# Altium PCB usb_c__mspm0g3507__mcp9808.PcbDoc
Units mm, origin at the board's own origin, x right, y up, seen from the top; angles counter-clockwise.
Board outline 68 x 40 mm, 2 copper layers (Top, Bottom), stack 0 mm thick; 37 components, 30 nets, 190 pads, 69 vias.
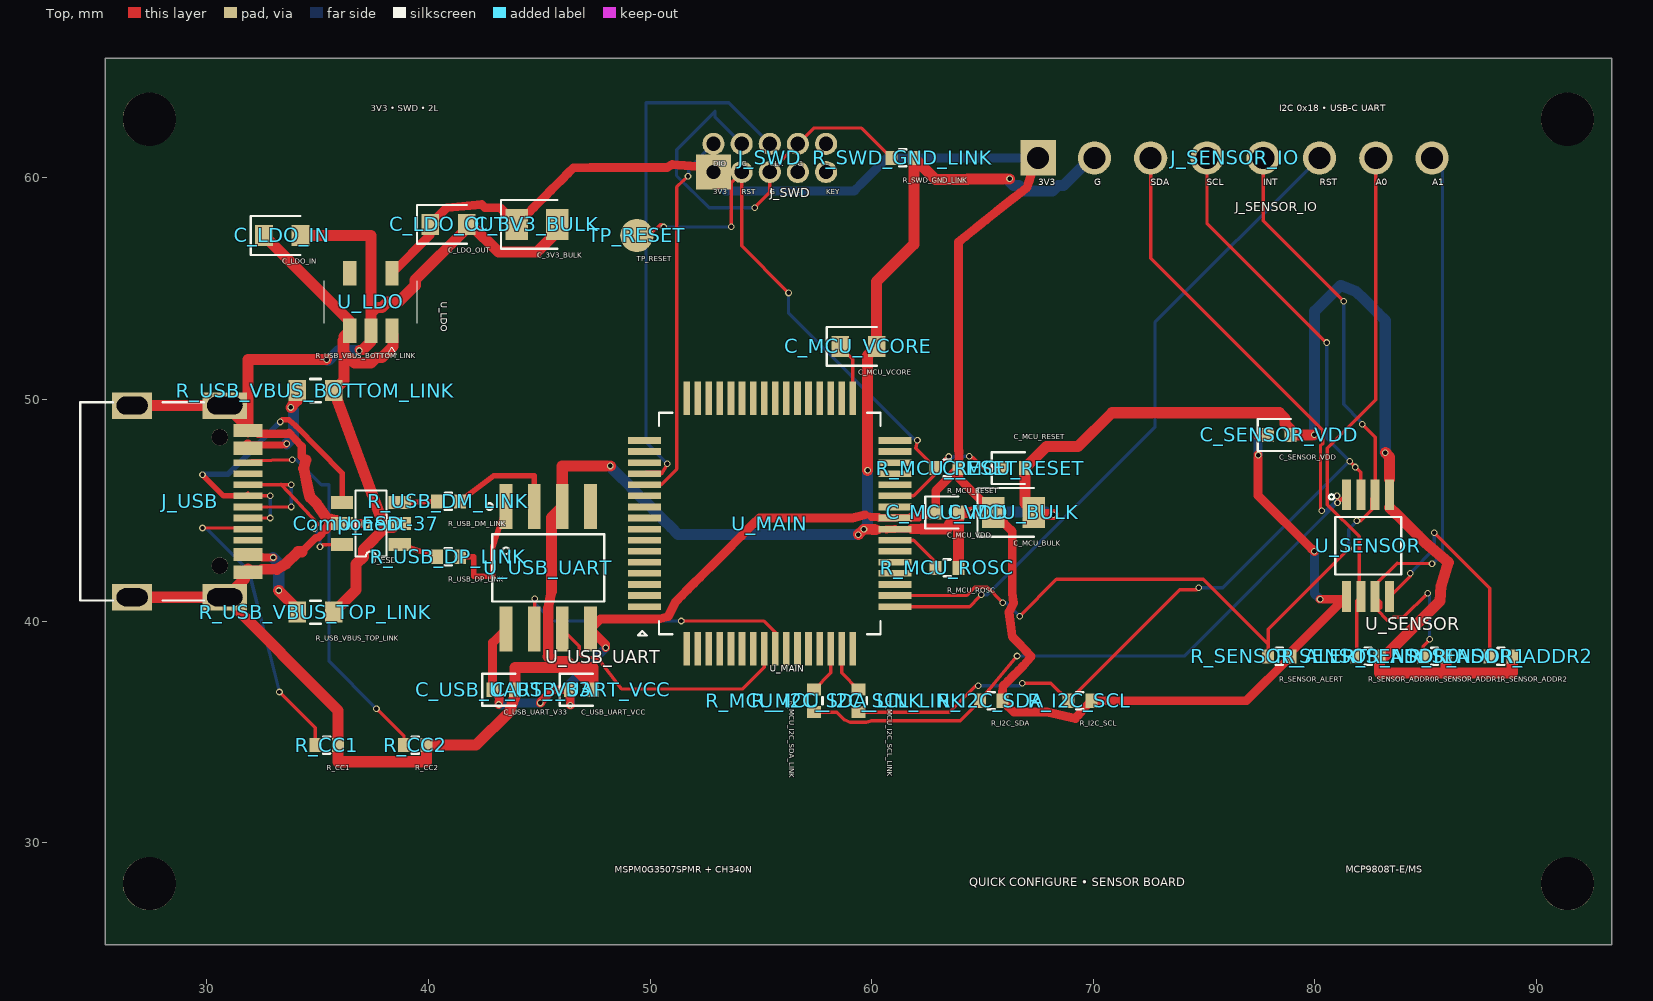
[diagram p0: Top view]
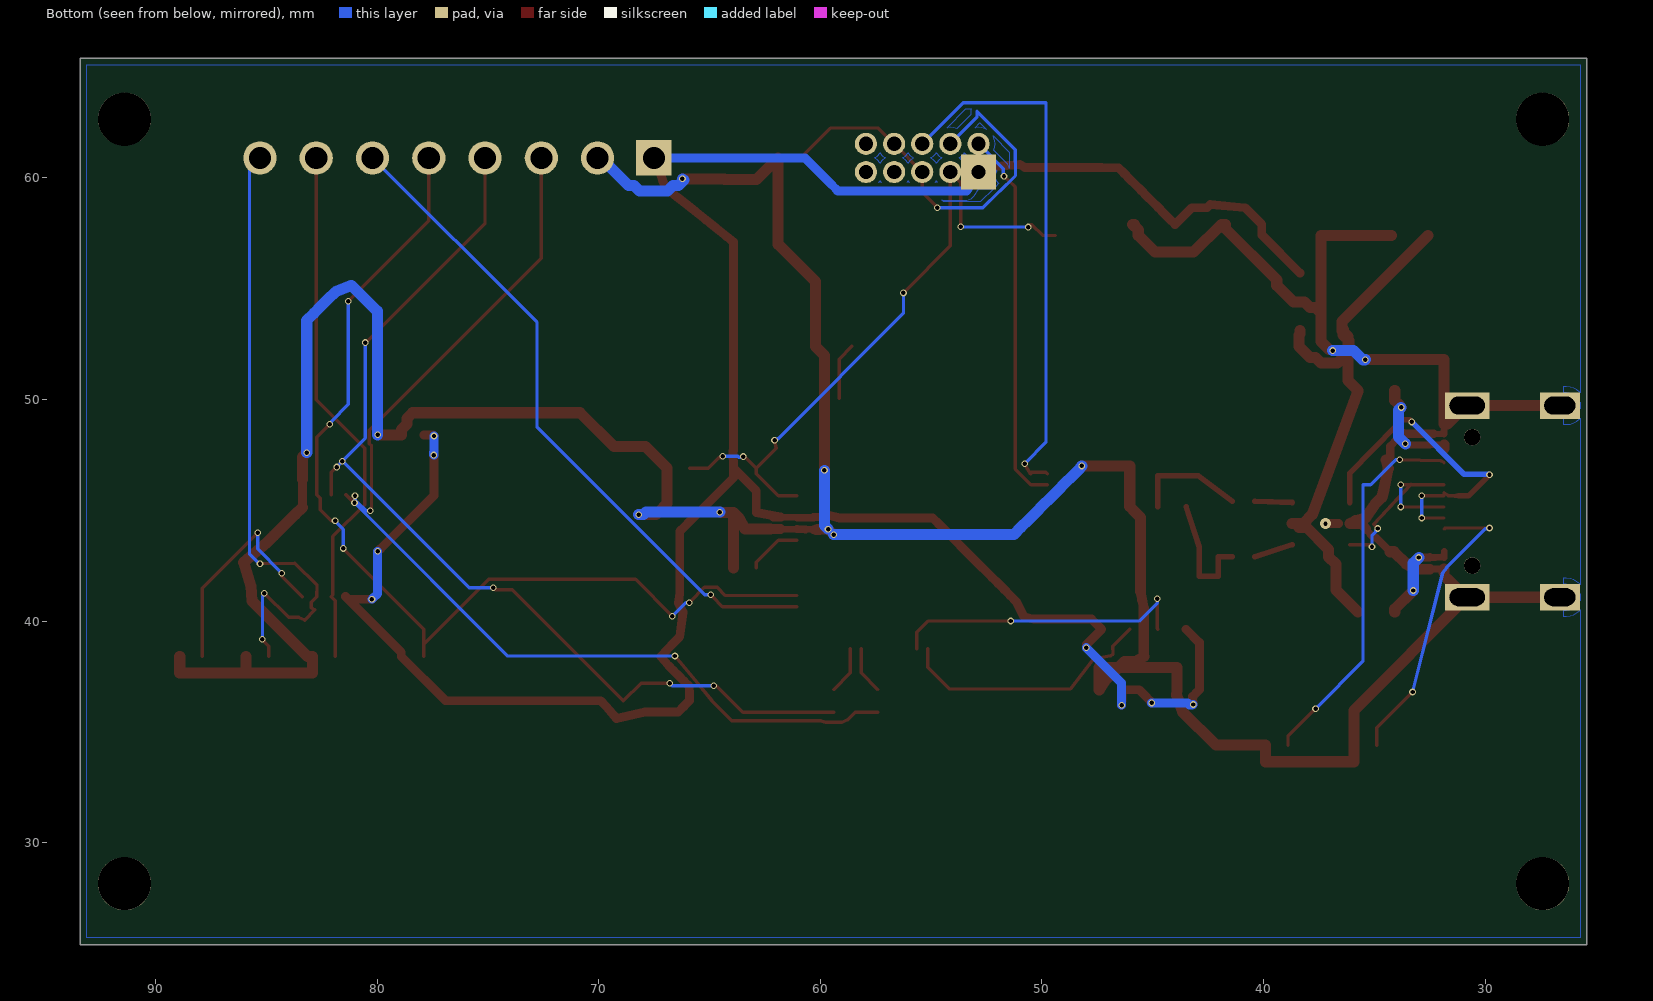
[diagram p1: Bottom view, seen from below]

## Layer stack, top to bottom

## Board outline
25.4,65.4 93.4,65.4 93.4,25.4 25.4,25.4

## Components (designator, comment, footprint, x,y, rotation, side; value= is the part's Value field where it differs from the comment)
C_3V3_BULK "" TSCIRCUIT-2.8500x1.4000mm 44.9,57.9 r0 top
C_LDO_IN "" TSCIRCUIT-2.4500x0.9500mm 33.4,57.4 r0 top
C_LDO_OUT "" TSCIRCUIT-2.4500x0.9500mm 40.9,57.9 r0 top
C_MCU_BULK "" TSCIRCUIT-2.8500x1.4000mm 66.4,44.9 r0 top
C_MCU_RESET "" TSCIRCUIT-1.5600x0.6400mm 66.4,46.9 r0 top
C_MCU_VCORE "" TSCIRCUIT-2.4500x0.9500mm 59.4,52.4 r0 top
C_MCU_VDD "" TSCIRCUIT-1.5600x0.6400mm 63.4,44.9 r0 top
C_SENSOR_VDD "" TSCIRCUIT-1.5600x0.6400mm 78.4,48.4 r0 top
C_USB_UART_V33 "" TSCIRCUIT-1.5600x0.6400mm 43.4,36.9 r0 top
C_USB_UART_VCC "" TSCIRCUIT-1.5600x0.6400mm 46.9,36.9 r0 top
Component-37 "" TSCIRCUIT-0.5000x0.5000mm 37.2,44.4 r0 top
J_SENSOR_IO "" TSCIRCUIT-19.2800x1.5000mm 76.4,60.9 r0 top
J_SWD "" TSCIRCUIT-6.0800x2.2700mm 55.4,60.9 r0 top
J_USB "" TSCIRCUIT-6.7732x9.8502mm 29.112,45.4 r90 top
R_CC1 "" TSCIRCUIT-1.5600x0.6400mm 35.4,34.4 r0 top
R_CC2 "" TSCIRCUIT-1.5600x0.6400mm 39.4,34.4 r0 top
R_I2C_SCL "" TSCIRCUIT-1.5600x0.6400mm 69.4,36.4 r0 top
R_I2C_SDA "" TSCIRCUIT-1.5600x0.6400mm 65.4,36.4 r0 top
R_MCU_I2C_SCL_LINK "" TSCIRCUIT-0.6400x1.5600mm 59.4,36.4 r270 top
R_MCU_I2C_SDA_LINK "" TSCIRCUIT-0.6400x1.5600mm 57.4,36.4 r270 top
R_MCU_RESET "" TSCIRCUIT-1.5600x0.6400mm 63.4,46.9 r0 top
R_MCU_ROSC "" TSCIRCUIT-1.5600x0.6400mm 63.4,42.4 r0 top
R_SENSOR_ADDR0 "" TSCIRCUIT-1.5600x0.6400mm 82.4,38.4 r0 top
R_SENSOR_ADDR1 "" TSCIRCUIT-1.5600x0.6400mm 85.4,38.4 r0 top
R_SENSOR_ADDR2 "" TSCIRCUIT-1.5600x0.6400mm 88.4,38.4 r0 top
R_SENSOR_ALERT "" TSCIRCUIT-1.5600x0.6400mm 78.4,38.4 r0 top
R_SWD_GND_LINK "" TSCIRCUIT-1.5600x0.6400mm 61.4,60.9 r0 top
R_USB_DM_LINK "" TSCIRCUIT-1.5600x0.6400mm 40.9,45.4 r0 top
R_USB_DP_LINK "" TSCIRCUIT-1.5600x0.6400mm 40.9,42.9 r0 top
R_USB_VBUS_BOTTOM_LINK "" TSCIRCUIT-2.4500x0.9500mm 34.9,50.4 r0 top
R_USB_VBUS_TOP_LINK "" TSCIRCUIT-2.4500x0.9500mm 34.9,40.4 r0 top
TP_RESET "" TSCIRCUIT-1.5000x1.5000mm 49.4,57.4 r0 top
U_ESD "" TSCIRCUIT-3.6000x2.5000mm 37.4,44.4 r0 top
U_LDO "" TSCIRCUIT-2.5000x3.7000mm 37.4,54.4 r270 top
U_MAIN "" TSCIRCUIT-12.8000x12.8000mm 55.4,44.4 r0 top
U_SENSOR "" TSCIRCUIT-2.3562x5.9969mm 82.4,43.4 r0 top
U_USB_UART "" TSCIRCUIT-4.3840x7.5712mm 45.4,42.4 r0 top

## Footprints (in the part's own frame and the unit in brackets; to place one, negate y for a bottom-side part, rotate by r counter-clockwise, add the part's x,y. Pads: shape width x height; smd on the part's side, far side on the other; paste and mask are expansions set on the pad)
TSCIRCUIT-0.5000x0.5000mm [mm]
TSCIRCUIT-0.6400x1.5600mm [mm]
  rect 0.54x0.64 smd: 1(-0.51,0) 2(0.51,0)
  silkscreen extent -0.15,-0.38 0.15,0.38
TSCIRCUIT-1.5000x1.5000mm [mm]
  round 1.5 smd: 1(0,0)
TSCIRCUIT-1.5600x0.6400mm [mm]
  rect 0.54x0.64 smd: 1(-0.51,0) 2(0.51,0)
  silkscreen extent -0.98,-0.72 0.51,0.72
TSCIRCUIT-2.3562x5.9969mm [mil]
  rect 15.98x55 smd: 1(-38.39,90.55) 2(-12.8,90.55) 3(12.8,90.55) 4(38.39,90.55) 5(38.39,-90.55) 6(12.8,-90.55) 7(-12.8,-90.55) 8(-38.39,-90.55)
  silkscreen extent -70,-51 59,91
TSCIRCUIT-2.4500x0.9500mm [mm]
  rect 0.8x0.95 smd: 1(-0.825,0) 2(0.825,0)
  silkscreen extent -1.42,-0.87 0.82,0.87
TSCIRCUIT-2.5000x3.7000mm [mm]
  rect 1.1x0.6 smd: 1(1.3,0.95) 2(1.3,0) 3(1.3,-0.95) 4(-1.3,-0.95) 5(-1.3,0.95)
  silkscreen extent -0.95,-2.1 2.35,2.1
TSCIRCUIT-2.8500x1.4000mm [mm]
  rect 1.025x1.4 smd: 1(-0.913,0) 2(0.913,0)
  silkscreen extent -1.62,-1.1 0.91,1.1
TSCIRCUIT-3.6000x2.5000mm [mm]
  rect 1x0.6 smd: 1(-1.3,-0.95) 2(-1.3,0) 3(-1.3,0.95) 4(1.3,0.95) 5(1.3,0) 6(1.3,-0.95)
  silkscreen extent -0.7,-1.49 0.7,1.49
TSCIRCUIT-4.3840x7.5712mm [mm]
  rect 0.574x2.036 smd: 1(-1.905,2.768) 2(-0.635,2.768) 3(0.635,2.768) 4(1.905,2.768) 5(1.905,-2.768) 6(0.635,-2.768) 7(-0.635,-2.768) 8(-1.905,-2.768)
  silkscreen extent -2.79,-1.52 2.53,2.92
TSCIRCUIT-6.0800x2.2700mm [mm]
  rect 1.6x1.6 hole 0.65: 1(-2.54,-0.635)
  round 1 hole 0.65: 2(-2.54,0.635) 3(-1.27,0.635) 4(0,0.635) 5(1.27,0.635) 6(2.54,0.635) 7(2.54,-0.635) 8(1.27,-0.635) 9(0,-0.635) 10(-1.27,-0.635)
TSCIRCUIT-6.7732x9.8502mm [mm]
  rect 0.3x1.3 smd: 1(-3.35,-2.737) 2(-3.05,-2.737) 3(-2.55,-2.737) 4(-2.25,-2.737) 5(-1.75,-2.737) 6(-1.25,-2.737) 7(-0.75,-2.737) 8(-0.25,-2.737) 9(0.25,-2.737) 10(0.75,-2.737) 11(1.25,-2.737) 12(1.75,-2.737) 13(2.55,-2.737) 14(2.25,-2.737) 15(3.35,-2.737) 16(3.05,-2.737)
  rect 1.2x2 hole 0.8 slot 1.6 at 90 deg: 17(-4.325,-1.693) 18(4.325,-1.693)
  rect 1.2x1.8 hole 0.8 slot 1.4 at 90 deg: 19(4.325,2.487) 20(-4.325,2.487)
  round 0.75 hole 0.75 unplated: NPTH-1(-2.9,-1.468) NPTH-2(2.9,-1.468)
  silkscreen extent -4.47,-0.75 4.47,4.83
TSCIRCUIT-12.8000x12.8000mm [mm]
  rect 1.5x0.3 smd: 1(-5.65,-3.75) 2(-5.65,-3.25) 3(-5.65,-2.75) 4(-5.65,-2.25) 5(-5.65,-1.75) 6(-5.65,-1.25) 7(-5.65,-0.75) 8(-5.65,-0.25) 9(-5.65,0.25) 10(-5.65,0.75) 11(-5.65,1.25) 12(-5.65,1.75) 13(-5.65,2.25) 14(-5.65,2.75) 15(-5.65,3.25) 16(-5.65,3.75) 33(5.65,3.75) 34(5.65,3.25) 35(5.65,2.75) 36(5.65,2.25) 37(5.65,1.75) 38(5.65,1.25) 39(5.65,0.75) 40(5.65,0.25) 41(5.65,-0.25) 42(5.65,-0.75) 43(5.65,-1.25) 44(5.65,-1.75) 45(5.65,-2.25) 46(5.65,-2.75) 47(5.65,-3.25) 48(5.65,-3.75)
  rect 0.3x1.5 smd: 17(-3.75,5.65) 18(-3.25,5.65) 19(-2.75,5.65) 20(-2.25,5.65) 21(-1.75,5.65) 22(-1.25,5.65) 23(-0.75,5.65) 24(-0.25,5.65) 25(0.25,5.65) 26(0.75,5.65) 27(1.25,5.65) 28(1.75,5.65) 29(2.25,5.65) 30(2.75,5.65) 31(3.25,5.65) 32(3.75,5.65) 49(3.75,-5.65) 50(3.25,-5.65) 51(2.75,-5.65) 52(2.25,-5.65) 53(1.75,-5.65) 54(1.25,-5.65) 55(0.75,-5.65) 56(0.25,-5.65) 57(-0.25,-5.65) 58(-0.75,-5.65) 59(-1.25,-5.65) 60(-1.75,-5.65) 61(-2.25,-5.65) 62(-2.75,-5.65) 63(-3.25,-5.65) 64(-3.75,-5.65)
  silkscreen extent -5.95,-5.05 5,5
TSCIRCUIT-19.2800x1.5000mm [mm]
  rect 1.6x1.6 hole 1: 1(-8.89,0)
  round 1.5 hole 1: 2(-6.35,0) 3(-3.81,0) 4(-1.27,0) 5(1.27,0) 6(3.81,0) 7(6.35,0) 8(8.89,0)

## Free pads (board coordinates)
  round 2.4 hole 2.4 unplated: NPTH-3(27.4,28.15) NPTH-4(91.4,28.15) NPTH-5(27.4,62.65) NPTH-6(91.4,62.65)

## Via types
v1: diameter 0.3, hole 0.2, Top to Bottom, 68 vias
v2: diameter 0.5, hole 0.2, Top to Bottom, 1 vias

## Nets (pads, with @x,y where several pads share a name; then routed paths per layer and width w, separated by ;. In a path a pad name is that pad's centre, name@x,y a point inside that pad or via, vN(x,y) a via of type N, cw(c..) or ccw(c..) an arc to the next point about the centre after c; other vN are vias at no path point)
".J_SWD > .pin2 to .U_MAIN > .pin12": J_SWD.2 U_MAIN.12 | length 17.1
  Top w0.15: U_MAIN.12 50.494,46.15 51.204,46.859 51.204,59.591 v1(51.709,60.071)
  Bottom w0.15: v1(51.709,60.071) 51.741,60.128 51.741,60.248 51.741,60.416 J_SWD.2
".J_SWD > .pin4 to .U_MAIN > .pin13": J_SWD.4 U_MAIN.13 | length 24.4
  Top w0.15: U_MAIN.13 49.819,46.719 50.52,46.719 50.509,46.646 50.708,46.977 v1(50.776,47.106)
  Bottom w0.15: v1(50.776,47.106) 50.75,47.132 49.816,48.066 49.816,63.384 53.551,63.384 J_SWD.4
".U_MAIN > .pin42 to .R_MCU_ROSC > .pin1": R_MCU_ROSC.1 U_MAIN.42 | length 2.5
  Top w0.15: U_MAIN.42 61.889,43.65 62.89,42.649 R_MCU_ROSC.1
GND: C_3V3_BULK.2 C_LDO_IN.2 C_LDO_OUT.2 C_MCU_BULK.2 C_MCU_RESET.2 C_MCU_VCORE.2 C_MCU_VDD.2 C_SENSOR_VDD.2 C_USB_UART_V33.2 C_USB_UART_VCC.2 J_SENSOR_IO.2 J_USB.1 J_USB.2 J_USB.15 J_USB.16 J_USB.17 J_USB.18 J_USB.19 J_USB.20 R_CC1.2 R_CC2.2 R_MCU_ROSC.2 R_SENSOR_ADDR0.2 R_SENSOR_ADDR1.2 R_SENSOR_ADDR2.2 R_SWD_GND_LINK.2 U_ESD.2 U_LDO.2 U_MAIN.41 U_SENSOR.4 U_USB_UART.3 | length 200.5
  Top w0.275: J_USB.16 J_USB.16@32.316,48.45
  Top w0.3: J_USB.1@31.699,41.9 J_USB.1 J_USB.1@31.849,42.2 ; J_USB.15@31.699,48.9 J_USB.15 ; J_USB.16@31.849,48.6 J_USB.15 ; J_USB.15@31.849,48.9 J_USB.15 ; 60.113,44.15 60.582,44.15 U_MAIN.41 61.144,44.15 61.238,44.15 61.331,44.15 61.425,44.15 61.519,44.15 61.613,44.15 61.706,44.15 61.8,44.15 ; 60.3,44.12 U_MAIN.41@60.675,44.135
  Top w0.312: J_USB.2 32.283,42.346 J_USB.2@32.499,42.344
  Top w0.325: J_USB.16 J_USB.16@31.849,48.6 ; 33.716,48.45 33.697,48.525 33.987,48.207 ; 34.278,43.127 34.596,43.445 34.914,43.762 35.025,43.759 35.181,43.916 35.366,44.157
  Top w0.35: 33.987,48.207 34.278,47.888
  Top w0.36: U_MAIN.41@60.675,44.135 U_MAIN.41
  Top w0.375: J_USB.16@32.316,48.45 32.782,48.45 33.249,48.45 33.716,48.45 ; v1@79.91,48.4 v1(79.98,48.4)
  Top w0.4: 34.278,47.888 34.278,47.425 34.462,47.275 ; 36.6,44.4 37.2,44.4 ; v1(36.878,52.207) v1@36.879,52.252 ; 60.175,44.12 60.3,44.12
  Top w0.406: U_SENSOR.4@83.375,45.129 83.375,45.414 U_SENSOR.4 83.375,46.398
  Top w0.425: v1@36.879,52.252 37.034,52.252
  Top w0.45: 35.366,44.157 35.551,44.398 ; 45.4,40.588 45.473,40.959 45.545,41.331 ; 61.8,44.15 62.253,44.15
  Top w0.475: 32.499,42.344 32.716,42.342 33.15,42.337 ; 45.4,38.4 45.4,38.837 45.4,39.275 45.4,39.713 45.4,40.15 45.4,40.588 ; v1@59.401,43.907 59.645,44.15 60.113,44.15 ; v1(59.65,44.15) 60.02,44.15 60.05,44.12 60.175,44.12
  Top w0.5: J_USB.20 J_USB.17 ; J_USB.19 J_USB.18 ; J_USB.18 30.874,49.725 31.474,49.125 31.699,48.9 ; 31.699,41.9 31.474,41.675 30.874,41.075 J_USB.17 35.91,35.971 R_CC1.2 35.91,33.65 39.91,33.65 R_CC2.2 42.15,34.4 43.65,35.9 43.921,36.642 C_USB_UART_V33.2 43.91,37.9 47.41,37.9 C_USB_UART_VCC.2 47.15,37.306 46.275,38.181 45.75,38.181 45.4,38.4 ; J_USB.1@31.849,42.2 J_USB.2 ; 31.849,48.9 31.849,51.8 v1(35.4,51.8) ; 33.15,42.337 33.555,42.573 34.108,43.127 34.278,43.127 ; C_LDO_IN.2 37.4,57.4 U_LDO.2 ; 34.462,47.275 34.37,46.887 34.556,45.962 34.65,45.588 34.963,45.275 35.4,44.65 35.844,44.525 U_ESD.2 35.825,44.399 35.551,44.398 ; 37.034,52.252 37.217,52.435 37.4,52.618 U_LDO.2 ; 45.545,41.331 45.545,41.81 45.545,42.288 45.545,42.766 45.545,43.244 45.545,43.722 45.545,44.2 45.545,44.678 45.79,44.923 U_USB_UART.3 46.035,47 v1(48.2,47) ; C_3V3_BULK.2 45.9,57.9 45.65,57.65 45.65,57.4 44.9,56.65 43.15,56.65 41.9,57.9 C_LDO_OUT.2 41.725,57.725 39.4,55.4 39.4,55.15 38.65,54.4 38.15,54.4 37.9,54.15 37.65,54.15 37.4,53.9 U_LDO.2 ; v1(59.397,43.902) v1@59.401,43.907 ; v1(59.813,46.799) 59.816,46.802 59.816,46.82 59.816,51.991 C_MCU_VCORE.2 60.225,52.887 60.225,53.374 60.225,53.86 60.225,54.347 60.225,54.834 60.225,55.321 61.91,57.006 R_SWD_GND_LINK.2 62.235,60.575 62.559,60.251 62.884,59.926 63.361,59.93 63.838,59.935 64.315,59.939 64.792,59.944 65.268,59.948 65.745,59.952 v1(66.222,59.957) ; 62.253,44.15 62.707,44.15 63.4,44.15 63.66,44.65 C_MCU_VDD.2 ; R_MCU_ROSC.2 C_MCU_VDD.2 ; v1(64.535,44.913) 64.522,44.9 C_MCU_VDD.2 ; v1(68.2,44.8) 67.412,44.8 C_MCU_BULK.2 66.91,45.303 C_MCU_RESET.2 67.883,47.873 69.312,47.873 70.839,49.4 78.4,49.4 78.65,49.15 78.65,48.9 78.91,48.64 C_SENSOR_VDD.2 79.41,48.4 v1@79.91,48.4 ; v1(83.18,47.6) 83.375,47.405 83.375,46.398 ; U_SENSOR.4@83.375,45.129 83.698,44.809 84.02,44.489 84.342,44.169 84.665,43.85 84.987,43.53 86.025,42.65 85.697,41.586 85.65,40.9 83.15,38.4 R_SENSOR_ADDR0.2 82.91,37.65 85.91,37.65 ; R_SENSOR_ADDR2.2 88.91,37.65 85.91,37.65 ; 85.91,37.65 R_SENSOR_ADDR1.2 85.91,37.65
  Bottom w0.5: v1(35.4,51.8) 35.423,51.777 35.505,51.777 35.72,51.992 35.935,52.207 36.406,52.207 v1(36.878,52.207) ; v1(48.2,47) 48.285,46.915 48.285,46.885 48.616,46.554 48.948,46.222 49.279,45.891 49.611,45.559 49.942,45.228 50.274,44.896 50.605,44.565 50.936,44.233 51.268,43.902 51.746,43.902 52.224,43.902 52.702,43.902 53.181,43.902 53.659,43.902 54.137,43.902 54.615,43.902 55.093,43.902 55.571,43.902 56.05,43.902 56.528,43.902 57.006,43.902 57.484,43.902 57.962,43.902 58.44,43.902 58.919,43.902 v1(59.397,43.902) ; v1(59.65,44.15) 59.813,44.313 v1(59.813,46.799) ; v1(64.535,44.913) 67.874,44.913 67.987,44.8 v1(68.2,44.8) ; v1(66.222,59.957) 66.165,59.9 66.15,59.9 66.4,59.65 66.65,59.65 66.9,59.4 68.15,59.4 68.4,59.65 68.65,59.65 69.9,60.9 J_SENSOR_IO.2 ; v1(79.98,48.4) 79.98,53.98 81.15,55.15 81.889,54.858 82.211,54.536 82.534,54.213 82.856,53.891 83.178,53.568 83.178,53.071 83.178,52.574 83.178,52.077 83.178,51.579 83.178,51.082 83.178,50.585 83.178,50.088 83.178,49.59 83.178,49.093 83.178,48.596 83.178,48.099 83.178,47.602 v1(83.18,47.6)
MAIN_RESET: C_MCU_RESET.1 J_SWD.10 R_MCU_RESET.1 TP_RESET.1 U_MAIN.38 | length 30.2
  Top w0.15: TP_RESET.1 49.961,57.4 50.448,57.887 50.514,57.887 v1(50.621,57.78) ; v1(53.655,57.789) 53.655,59.79 J_SWD.10 54.13,56.926 56.178,54.878 v1(56.248,54.808) ; U_MAIN.38 61.889,45.65 62.89,46.651 R_MCU_RESET.1 ; v1(62.065,48.153) 61.99,47.8 R_MCU_RESET.1 ; v1(63.471,47.424) 63.393,47.403 R_MCU_RESET.1 ; v1(64.409,47.441) 64.478,47.372 64.586,47.372 65.058,46.9 C_MCU_RESET.1
  Bottom w0.15: v1(50.621,57.78) 53.602,57.78 53.614,57.767 53.633,57.767 v1(53.655,57.789) ; v1(56.248,54.808) 56.248,53.882 61.902,48.229 61.914,48.229 v1(62.065,48.153) ; v1(63.471,47.424) 63.499,47.392 63.68,47.392 63.729,47.441 v1(64.409,47.441)
MCU_I2C_SCL_LOCAL: R_MCU_I2C_SCL_LINK.1 U_MAIN.50 | length 2.2
  Top w0.15: U_MAIN.50 58.65,37.66 R_MCU_I2C_SCL_LINK.1
MCU_I2C_SDA_LOCAL: R_MCU_I2C_SDA_LINK.1 U_MAIN.51 | length 2.2
  Top w0.15: R_MCU_I2C_SDA_LINK.1 58.15,37.66 U_MAIN.51
MSPM0_VCORE: C_MCU_VCORE.1 U_MAIN.32 | length 2.6
  Top w0.15: C_MCU_VCORE.1 59.15,51.825 U_MAIN.32
SENSOR_ADDR0: J_SENSOR_IO.7 R_SENSOR_ADDR0.1 U_SENSOR.7 | length 24.1
  Top w0.15: R_SENSOR_ADDR0.1 81.89,40.915 U_SENSOR.7 81.997,41.177 81.997,43.817 80.565,45.25 80.565,47.806 82.75,49.991 J_SENSOR_IO.7
SENSOR_ADDR1: J_SENSOR_IO.8 R_SENSOR_ADDR1.1 U_SENSOR.6 | length 29
  Top w0.15: R_SENSOR_ADDR1.1 84.89,38.857 85.097,39.064 85.097,39.1 v1(85.178,39.181) ; v1(85.088,41.257) 83.997,40.166 83.542,40.166 83.266,40.04 82.806,40.505 82.967,40.588 82.967,40.858 U_SENSOR.6 82.713,41.612 83.722,42.608 v1(85.286,42.592)
  Bottom w0.15: v1(85.088,41.257) 85.118,41.227 85.118,41.155 85.178,41.095 v1(85.178,39.181) ; v1(85.286,42.592) 85.41,42.679 85.763,43.032 85.763,43.096 85.763,60.427 J_SENSOR_IO.8
SENSOR_ADDR2: R_SENSOR_ADDR2.1 U_SENSOR.5 | length 10.3
  Top w0.15: U_SENSOR.5 84.3,42.025 v1(84.3,42.159) ; v1(85.394,43.985) 85.481,43.898 87.89,41.489 R_SENSOR_ADDR2.1
  Bottom w0.15: v1(84.3,42.159) 84.322,42.181 85.394,43.253 v1(85.394,43.985)
SENSOR_INT: J_SENSOR_IO.5 R_SENSOR_ALERT.1 U_MAIN.47 U_SENSOR.3 | length 46.7
  Top w0.15: U_MAIN.47 64.279,41.15 64.647,41.519 65.23,41.52 65.878,40.87 65.878,40.861 v1(65.907,40.832) ; v1(66.681,40.218) 68.339,41.88 74.973,41.88 77.89,38.963 R_SENSOR_ALERT.1 77.89,39.638 81.434,43.182 81.439,43.182 v1(81.534,43.277) ; J_SENSOR_IO.5 77.67,58.069 81.148,54.591 81.148,54.58 v1(81.3,54.428) ; v1(81.9,44.532) 82.074,44.531 82.563,45.017 82.561,45.535 U_SENSOR.3 82.725,48.295 v1(82.144,48.876)
  Bottom w0.15: v1(65.907,40.832) 66.063,40.832 66.657,40.238 v1(66.681,40.218) ; v1(81.3,54.428) 81.3,49.779 82.077,49.001 82.077,48.943 v1(82.144,48.876) ; v1(81.534,43.277) 81.534,44.134 81.811,44.411 81.811,44.443 v1(81.9,44.532)
SENSOR_RESET: J_SENSOR_IO.6 U_MAIN.48 | length 30.3
  Top w0.15: U_MAIN.48 64.418,40.65 64.865,41.097 64.867,41.097 v1(64.952,41.18)
  Bottom w0.15: v1(64.952,41.18) 65.215,41.182 72.784,48.751 72.784,53.474 J_SENSOR_IO.6
SENSOR_SCL: J_SENSOR_IO.4 R_I2C_SCL.1 R_MCU_I2C_SCL_LINK.2 U_SENSOR.2 | length 47.3
  Top w0.15: R_MCU_I2C_SCL_LINK.2 63.49,35.89 64.664,37.064 64.79,37.064 v1(64.81,37.084) ; v1(66.8,37.199) 68.091,37.199 R_I2C_SCL.1 73.897,41.407 74.566,41.407 74.676,41.407 v1(74.768,41.499) ; J_SENSOR_IO.4 75.13,57.956 80.433,52.652 80.448,52.652 v1(80.532,52.568) ; v1(81.58,47.209) 82.075,46.714 ; v1(81.825,46.95) 82.075,46.714 ; 82.075,46.714 U_SENSOR.2 82.075,46.714
  Bottom w0.15: v1(64.81,37.084) 66.675,37.084 66.77,37.179 66.78,37.179 v1(66.8,37.199) ; v1(74.768,41.499) 75.843,41.499 81.551,47.206 81.577,47.206 v1(81.825,46.95) ; v1(80.532,52.568) 80.532,48.257 81.557,47.232 v1(81.58,47.209)
SENSOR_SDA: J_SENSOR_IO.3 R_I2C_SDA.1 R_MCU_I2C_SDA_LINK.2 U_SENSOR.1 | length 49.7
  Top w0.15: R_MCU_I2C_SDA_LINK.2 58.417,35.89 58.758,35.548 59.032,35.43 59.3,35.43 59.55,35.429 59.764,35.43 60,35.502 59.987,35.502 63.992,35.502 R_I2C_SDA.1 65.639,37.325 v1(66.561,38.421) ; J_SENSOR_IO.3 72.59,56.374 80.35,48.614 80.35,48.001 80.254,47.905 80.254,45.044 80.288,45.011 80.288,44.996 v1(80.305,44.979) ; v1(81,45.65) 81.058,45.333 U_SENSOR.1 81.389,45.7 81.064,45.376 v1(81.022,45.333)
  Bottom w0.15: v1(66.561,38.421) 66.637,38.421 74.11,38.421 v1(81.022,45.333) ; v1(80.305,44.979) 80.496,44.979 80.89,45.372 80.983,45.372 v1(81,45.65)
swd-ground-1-to-2: J_SWD.3 J_SWD.5 J_SWD.9 R_SWD_GND_LINK.1 | length 18.5
  Top w0.15: v1(54.717,58.649) 54.806,58.738 54.806,58.761 55.4,59.355 J_SWD.9 J_SWD.5 57.382,62.247 59.375,62.247 59.543,62.247 R_SWD_GND_LINK.1
  Bottom w0.15: J_SWD.3 52.931,62.734 52.931,63.008 51.201,61.278 51.191,60.106 52.665,58.647 v1(54.717,58.649)
UART_MSP_RX: U_MAIN.57 U_USB_UART.6 | length 11.8
  Top w0.15: U_USB_UART.6 46.807,38.86 46.791,38.493 46.894,38.439 47.666,38.287 48.711,36.929 54.165,36.929 55.15,37.914 U_MAIN.57
UART_MSP_TX: U_MAIN.56 U_USB_UART.7 | length 13.7
  Top w0.15: U_USB_UART.7 44.8,39.667 v1(44.8,41) ; v1(51.4,40.001) 51.401,40 51.642,40 55.142,40 55.65,39.492 U_MAIN.56
  Bottom w0.15: v1(44.8,41) 44.778,40.978 44.778,40.836 45.614,40.001 v1(51.4,40.001)
usb-dm-device: R_USB_DM_LINK.1 U_ESD.4 | length 1.7
  Top w0.25: U_ESD.4 R_USB_DM_LINK.1
usb-dm-port-tie: J_USB.7 J_USB.9 U_ESD.3 | length 15.4
  Top w0.15: J_USB.9@31.349,45.65 31.38,45.65 31.474,45.65 31.568,45.65 31.601,45.65 31.662,45.65 31.615,45.65 31.849,45.79 J_USB.9 v1(32.85,45.65) ; J_USB.7 v1(32.85,44.65)
  Top w0.175: J_USB.9@31.287,45.65 J_USB.9@31.349,45.65
  Top w0.212: 31.193,45.65 J_USB.9@31.287,45.65
  Top w0.25: v1(29.8,46.6) 30.75,45.65 31.099,45.65 31.193,45.65 ; v1(33.303,48.985) 33.397,49.079 33.692,49.079 34.015,48.798 36.1,46.671 U_ESD.3
  Bottom w0.15: v1(32.85,44.65) v1(32.85,45.65)
  Bottom w0.25: v1(29.8,46.6) 29.825,46.625 29.842,46.625 30.943,46.625 v1(33.303,48.985)
usb-dm-uart: R_USB_DM_LINK.2 U_USB_UART.2 | length 5.1
  Top w0.25: R_USB_DM_LINK.2 42.95,46.55 44.765,46.55 U_USB_UART.2
usb-dp-device: R_USB_DP_LINK.1 U_ESD.6 | length 1.8
  Top w0.25: U_ESD.6 R_USB_DP_LINK.1
usb-dp-port-tie: J_USB.8 J_USB.10 U_ESD.1 | length 11.1
  Top w0.15: J_USB.8 v1(33.8,45.15) ; v1(33.8,46.15) J_USB.10 32.905,46.15 33.342,46.179 35.024,44.371 v1(34.848,44.177) ; v1(35.102,43.347) 35.113,43.358 35.138,43.358 35.231,43.45 U_ESD.1
  Bottom w0.15: v1(33.8,45.15) v1(33.8,46.15) ; v1(34.848,44.177) 34.935,44.09 34.935,44.027 35.102,43.86 v1(35.102,43.347)
usb-dp-uart: R_USB_DP_LINK.2 U_USB_UART.1 | length 5.6
  Top w0.25: R_USB_DP_LINK.2 42.05,42.9 42.05,42.03 42.9,42.03 42.9,43.35 U_USB_UART.1
USB_CC1: J_USB.6 R_CC1.1 | length 13.7
  Top w0.15: v1(29.8,44.2) 31.799,44.2 J_USB.6 ; v1(33.271,36.799) 33.33,36.74 34.89,35.18 R_CC1.1
  Bottom w0.15: v1(29.8,44.2) 29.835,44.165 29.991,44.165 31.727,42.429 31.725,42.406 31.911,42.18 v1(33.271,36.799)
USB_CC2: J_USB.12 R_CC2.1 | length 17.3
  Top w0.15: J_USB.12 32,47.237 v1(33.848,47.284) ; v1(37.649,36.046) 37.755,35.94 37.779,35.94 38.89,34.828 R_CC2.1
  Bottom w0.15: v1(33.848,47.284) 34.039,47.284 35.166,46.158 35.508,46.158 35.508,38.187 v1(37.649,36.046)
USB_VBUS_BOTTOM_LOCAL: J_USB.13 J_USB.14 R_USB_VBUS_BOTTOM_LINK.1 | length 4.8
  Top w0.3: J_USB.14 J_USB.14@31.849,47.8 ; J_USB.13 J_USB.13@32.499,47.95
  Top w0.325: 32.499,47.95 33.545,47.95 v1(33.595,48)
  Top w0.475: J_USB.13@31.849,47.8 J_USB.13
  Top w0.5: v1(33.787,49.64) 33.855,49.708 33.855,49.741 34.075,49.962 R_USB_VBUS_BOTTOM_LINK.1
  Bottom w0.5: v1(33.595,48) 33.9,48.305 33.9,48.9 33.9,49.527 v1(33.787,49.64)
USB_VBUS_TOP_LOCAL: J_USB.3 J_USB.4 R_USB_VBUS_TOP_LINK.1 | length 4.4
  Top w0.3: J_USB.4 31.849,43 J_USB.3 J_USB.3@31.868,42.877
  Top w0.309: J_USB.3@31.868,42.877 32.242,42.874 J_USB.3@32.499,42.873
  Top w0.375: 32.499,42.873 32.615,42.872 v1(32.989,42.869)
  Top w0.5: v1(33.239,41.379) 34.075,40.544 R_USB_VBUS_TOP_LINK.1
  Bottom w0.5: v1(32.989,42.869) 33.239,42.619 v1(33.239,41.379)
VBUS5: C_LDO_IN.1 R_USB_VBUS_BOTTOM_LINK.2 R_USB_VBUS_TOP_LINK.2 U_ESD.5 U_LDO.1 U_LDO.3 | length 26.1
  Top w0.5: C_LDO_IN.1 36.45,53.525 U_LDO.3 ; R_USB_VBUS_TOP_LINK.2 35.733,40.4 36.733,41.4 36.733,42.567 37.067,42.9 37.067,43.233 38.067,44.233 38.4,44.233 38.567,44.4 U_ESD.5 38.2,44.4 37.8,44.8 R_USB_VBUS_BOTTOM_LINK.2 36.19,50.865 36.19,50.883 36.19,52.84 U_LDO.3 ; U_LDO.1 38.35,52.95 38.4,52.9 38.4,52.4 37.9,51.9 37.65,51.9 37.4,51.65 36.65,51.65 36.15,52.15 36.15,52.65 36.4,52.9 36.4,53.15 U_LDO.3
VCC_3V3: C_3V3_BULK.1 C_LDO_OUT.1 C_MCU_BULK.1 C_MCU_VDD.1 C_SENSOR_VDD.1 C_USB_UART_V33.1 C_USB_UART_VCC.1 J_SENSOR_IO.1 J_SWD.1 R_I2C_SCL.2 R_I2C_SDA.2 R_MCU_RESET.2 R_SENSOR_ALERT.2 U_LDO.5 U_MAIN.40 U_SENSOR.8 U_USB_UART.5 U_USB_UART.8 | length 125.2
  Top w0.3: 60.285,44.65 60.667,44.65 U_MAIN.40 ; U_MAIN.40@60.3,44.685 60.34,44.685 60.695,44.685 61.05,44.685 61.405,44.685 U_MAIN.40@61.76,44.685
  Top w0.312: 59.7,44.8 59.992,44.725 60.285,44.65 ; U_MAIN.40@60.695,44.662 U_MAIN.40
  Top w0.332: U_MAIN.40@61.797,44.692 U_MAIN.40@61.8,44.692
  Top w0.337: U_MAIN.40@60.34,44.673 U_MAIN.40@60.695,44.662
  Top w0.363: 60.3,44.685 59.985,44.685 U_MAIN.40@60.34,44.673
  Top w0.4: U_LDO.5 40.075,57.425 C_LDO_OUT.1 40.327,58.152 40.578,58.403 40.83,58.655 42.4,58.8 42.546,58.655 42.89,58.655 43.233,58.655 43.484,58.403 43.736,58.152 C_3V3_BULK.1 44.243,58.156 44.499,58.412 44.754,58.668 45.01,58.924 45.265,59.179 45.521,59.435 45.776,59.691 46.032,59.947 46.287,60.203 46.543,60.459 46.926,60.46 47.309,60.461 47.692,60.462 48.075,60.463 48.458,60.464 48.841,60.465 49.224,60.466 49.606,60.467 49.989,60.469 50.372,60.47 50.755,60.471 51,60.6 52.67,60.476 J_SWD.1 ; v1(43.168,36.232) 43.2,36.59 43.045,36.745 C_USB_UART_V33.1 42.89,39.027 U_USB_UART.8 ; v1(45.046,36.304) 45.101,36.359 45.101,36.39 45.357,36.645 45.612,36.9 46.001,36.9 C_USB_UART_VCC.1 46.39,36.405 46.393,36.401 46.393,36.207 v1(46.4,36.2) ; v1(48,38.8) 48,38.937 U_USB_UART.5 47.533,39.86 47.76,40.087 48.132,40.087 48.504,40.087 48.877,40.087 49.249,40.087 49.621,40.087 49.993,40.087 50.366,40.087 50.8,40.2 51.171,40.892 51.439,41.161 51.708,41.429 51.976,41.697 52.244,41.966 52.513,42.234 52.781,42.503 53.05,42.771 53.318,43.04 53.587,43.308 53.855,43.576 54.123,43.845 54.392,44.113 54.66,44.382 54.929,44.65 55.311,44.65 55.694,44.65 56.076,44.65 56.459,44.65 56.842,44.65 57.224,44.65 57.607,44.65 57.989,44.65 58.372,44.65 58.754,44.65 59.137,44.65 59.7,44.8 ; U_MAIN.40@61.76,44.685 62.115,44.685 61.8,44.692 ; U_MAIN.40@61.797,44.692 C_MCU_VDD.1 62.89,45.88 R_MCU_RESET.2 ; J_SENSOR_IO.1 67.288,60.678 67.311,60.469 67.21,60.171 67.109,59.873 67.008,59.575 66.699,59.328 66.39,59.081 66.081,58.834 65.772,58.588 65.463,58.341 65.154,58.094 64.845,57.848 64.535,57.601 64.226,57.354 63.917,57.108 63.917,56.715 63.917,56.322 63.916,55.93 63.916,55.537 63.916,55.145 63.916,54.752 63.915,54.359 63.915,53.967 63.915,53.574 63.914,53.182 63.914,52.789 63.914,52.396 63.914,52.004 63.913,51.611 63.913,51.219 63.913,50.826 63.913,50.433 63.912,50.041 63.912,49.648 63.912,49.256 63.911,48.863 63.911,48.47 63.911,48.078 63.911,47.685 63.933,47.667 R_MCU_RESET.2 ; v1(77.434,48.352) 77.482,48.4 77.64,48.4 C_SENSOR_VDD.1 ; v1(77.442,47.491) 77.442,45.659 79.847,43.253 79.87,43.253 v1(79.98,43.143) ; v1(80.234,40.982) 81.307,40.982 U_SENSOR.8 78.91,38.585 R_SENSOR_ALERT.2 76.91,36.4 R_I2C_SCL.2 69.66,36.144 69.2,35.6 67.91,35.892 67.535,35.894 67.16,35.895 66.784,35.896 66.409,35.897 66.16,36.149 R_I2C_SDA.2 65.911,36.725 65.912,37.05 66.15,37.289 66.388,37.527 66.626,37.765 66.864,38.004 67.2,38.4 66.621,39.018 66.34,39.295 66.2,40.4 66.4,40.8 66.341,41.257 66.341,41.65 66.342,42.042 66.342,42.435 66.342,42.828 66.342,43.22 66.342,43.613 66.343,44.005 66.343,44.045 66.129,44.258 65.915,44.472 65.701,44.686 C_MCU_BULK.1 63.91,46.478 R_MCU_RESET.2
  Bottom w0.4: v1(43.168,36.232) 43.219,36.219 43.332,36.219 43.417,36.304 43.743,36.304 44.069,36.304 44.395,36.304 44.72,36.304 v1(45.046,36.304) ; v1(46.4,36.2) 46.4,37.2 47.989,38.789 v1(48,38.8) ; J_SWD.1 53.4,59.4 59.2,59.4 59.292,59.498 59.573,59.779 59.853,60.059 60.133,60.339 60.414,60.62 60.694,60.9 61.073,60.9 61.451,60.9 61.83,60.9 62.209,60.9 62.587,60.9 62.966,60.9 63.345,60.9 63.723,60.9 64.102,60.9 64.481,60.9 64.859,60.9 65.238,60.9 65.617,60.9 65.995,60.9 66.374,60.9 66.753,60.9 67.131,60.9 J_SENSOR_IO.1 ; v1(77.434,48.352) 77.434,47.632 77.455,47.612 77.455,47.518 v1(77.442,47.491) ; v1(79.98,43.143) 79.98,41.236 80.218,40.998 v1(80.234,40.982)
pads on no net: J_SWD.6 J_SWD.7 J_SWD.8 J_USB.5 J_USB.11 J_USB.NPTH-1 J_USB.NPTH-2 U_LDO.4 U_MAIN.1 U_MAIN.2 U_MAIN.3 U_MAIN.4 U_MAIN.5 U_MAIN.6 U_MAIN.7 U_MAIN.8 U_MAIN.9 U_MAIN.10 U_MAIN.11 U_MAIN.14 U_MAIN.15 U_MAIN.16 U_MAIN.17 U_MAIN.18 U_MAIN.19 U_MAIN.20 U_MAIN.21 U_MAIN.22 U_MAIN.23 U_MAIN.24 U_MAIN.25 U_MAIN.26 U_MAIN.27 U_MAIN.28 U_MAIN.29 U_MAIN.30 U_MAIN.31 U_MAIN.33 U_MAIN.34 U_MAIN.35 U_MAIN.36 U_MAIN.37 U_MAIN.39 U_MAIN.43 U_MAIN.44 U_MAIN.45 U_MAIN.46 U_MAIN.49 U_MAIN.52 U_MAIN.53 U_MAIN.54 U_MAIN.55 U_MAIN.58 U_MAIN.59 U_MAIN.60 U_MAIN.61 U_MAIN.62 U_MAIN.63 U_MAIN.64 U_USB_UART.4
copper on no net:
  other v2: 37.2,44.4

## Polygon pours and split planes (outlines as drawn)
GND on Bottom (solid): 93.1,65.1 25.7,65.1 25.7,50.296 25.725,50.326 25.854,50.432 26.001,50.51 26.16,50.559 26.326,50.575 26.476,50.575 26.476,50.325 26.326,50.325 26.209,50.314 26.096,50.279 25.993,50.224 25.902,50.149 25.827,50.058 25.772,49.955 25.747,49.875 25.7,49.875 25.7,49.575 25.747,49.575 25.772,49.496 25.827,49.392 25.902,49.301 25.993,49.226 26.096,49.171 26.209,49.137 26.326,49.125 26.476,49.125 26.476,48.875 26.326,48.875 26.16,48.891 26.001,48.94 25.854,49.018 25.725,49.124 25.7,49.154 25.7,41.646 25.725,41.676 25.854,41.782 26.001,41.86 26.16,41.909 26.326,41.925 26.476,41.925 26.476,41.675 26.326,41.675 26.209,41.663 26.096,41.629 25.993,41.574 25.902,41.499 25.827,41.408 25.772,41.304 25.747,41.225 25.7,41.225 25.7,40.925 25.747,40.925 25.772,40.845 25.827,40.742 25.902,40.651 25.993,40.576 26.096,40.521 26.209,40.486 26.326,40.475 26.476,40.475 26.476,40.225 26.326,40.225 26.16,40.241 26.001,40.29 25.854,40.368 25.725,40.474 25.7,40.504 25.7,25.7 93.1,25.7
GND on Bottom (solid): 53.437,63.109 53.186,63.109 53.2,63.062 53.206,63.008 53.206,62.848 53.832,62.222 53.843,62.228 53.984,62.271 54.13,62.285 54.275,62.271
GND on Bottom (solid): 52.794,62.482 52.501,62.189 52.573,62.228 52.714,62.271 52.86,62.285 53.005,62.271
GND on Bottom (solid): 53.495,61.14 53.484,61.118 53.399,61.015 53.591,61.015 53.506,61.118
GND on Bottom (solid): 53.61,60.996 53.61,60.804 53.713,60.889 53.735,60.9 53.713,60.911
GND on Bottom (solid): 57.305,61.14 57.294,61.118 57.2,61.005 57.087,60.911 57.065,60.9 57.087,60.889 57.2,60.795 57.294,60.682 57.305,60.66 57.316,60.682 57.41,60.795 57.523,60.889 57.545,60.9 57.523,60.911 57.41,61.005 57.316,61.118
GND on Bottom (solid): 56.035,61.14 56.024,61.118 55.93,61.005 55.817,60.911 55.795,60.9 55.817,60.889 55.93,60.795 56.024,60.682 56.035,60.66 56.046,60.682 56.14,60.795 56.253,60.889 56.275,60.9 56.253,60.911 56.14,61.005 56.046,61.118
GND on Bottom (solid): 54.765,61.14 54.754,61.118 54.66,61.005 54.547,60.911 54.525,60.9 54.547,60.889 54.66,60.795 54.754,60.682 54.765,60.66 54.776,60.682 54.87,60.795 54.983,60.889 55.005,60.9 54.983,60.911 54.87,61.005 54.776,61.118
GND on Bottom (solid): 52.206,61.894 51.475,61.163 51.469,60.439 51.472,60.47 51.487,60.522 51.513,60.569 51.547,60.611 52.173,61.237 52.167,61.248 52.124,61.389 52.11,61.535 52.124,61.681 52.167,61.822
GND on Bottom (solid): 57.305,59.87 57.294,59.848 57.254,59.8 57.356,59.8 57.316,59.848
GND on Bottom (solid): 56.035,59.87 56.024,59.848 55.984,59.8 56.086,59.8 56.046,59.848
GND on Bottom (solid): 54.765,59.87 54.754,59.848 54.714,59.8 54.816,59.8 54.776,59.848
GND on Bottom (solid): 52.11,60.396 52.026,60.312 52.042,60.293 52.079,60.224 52.102,60.149 52.109,60.071 52.102,59.993 52.079,59.918 52.042,59.849 51.992,59.788 51.943,59.748 52.11,59.583
GND on Bottom (solid): 52.857,59.515 52.179,59.515 52.778,58.922 54.427,58.924 54.434,58.932 54.495,58.982 54.529,59 53.4,59 53.322,59.008 53.247,59.03 53.178,59.067 53.117,59.117 53.067,59.178 53.062,59.189 53.061,59.188

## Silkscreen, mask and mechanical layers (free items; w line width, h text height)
Top Overlay:
  text "3V3 • SWD • 2L" at 37.4,62.9 h0.48
  text "I2C 0x18 • USB-C UART" at 78.4,62.9 h0.5
  text "MSPM0G3507SPMR + CH340N" at 48.4,28.525 h0.52
  text "MCP9808T-E/MS" at 81.4,28.525 h0.55
  text "QUICK CONFIGURE • SENSOR BOARD" at 64.4,27.9 h0.65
